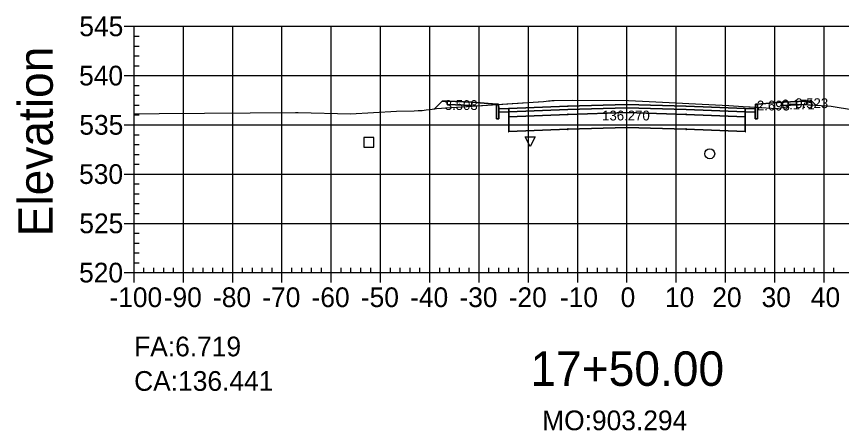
# Model space of a CAD drawing. Extents: x 704834 to 709892, y 372981 to 377533.
# Drawn here: x 704913 to 705080.4, y 374150.8 to 374234.8 of the extents above; entities that cross this region are included whole.
import ezdxf

# ---------------------------------------------------------------- set-up
doc = ezdxf.new("R2010")
doc.units = 0
for name, color, linetype in [('1', 7, 'Continuous'), ('10', 7, 'Continuous'), ('13', 7, 'Continuous'), ('14', 7, 'Continuous'), ('57', 7, 'Continuous'), ('59', 7, 'Continuous'), ('60', 7, 'Continuous'), ('Default_Xsect', 7, 'Continuous'), ('Existing', 7, 'Continuous')]:
    doc.layers.add(name, color=color, linetype=linetype)

msp = doc.modelspace()

# ---------------------------------------------------------------- linework, layer by layer
for points in [[(704999.37, 374217.61), (704997.84, 374216.07)], [(705000.37, 374217.65), (704999.37, 374217.61)], [(705010.37, 374217.05), (705005.37, 374217.45)], [(705063.37, 374217.05), (705068.37, 374217.45)], [(705073.37, 374217.65), (705074.37, 374217.61)], [(705074.37, 374217.61), (705075.16, 374216.82)]]:
    msp.add_lwpolyline(points)
for points in [[(705005.37, 374217.45), (705000.37, 374217.65), (705000.37, 374216.98), (705005.37, 374216.78)], [(705068.37, 374216.78), (705073.37, 374216.98), (705073.37, 374217.65), (705068.37, 374217.45)], [(705010.87, 374216.05), (705010.79, 374217.05), (705010.37, 374217.05), (705010.37, 374214.05), (705010.87, 374214.05)], [(705012.87, 374216.13), (705010.87, 374216.05), (705010.87, 374215.38), (705012.87, 374215.46)], [(705036.87, 374216.3), (705048.87, 374215.94), (705060.87, 374215.46), (705060.87, 374216.13), (705048.87, 374216.61), (705036.87, 374216.97), (705024.87, 374216.61), (705012.87, 374216.13), (705012.87, 374215.46), (705024.87, 374215.94)], [(705036.87, 374215.3), (705048.87, 374214.94), (705060.87, 374214.46), (705060.87, 374215.46), (705048.87, 374215.94), (705036.87, 374216.3), (705024.87, 374215.94), (705012.87, 374215.46), (705012.87, 374214.46), (705024.87, 374214.94)], [(705036.82, 374216.25), (705036.92, 374216.25), (705036.92, 374216.35), (705036.82, 374216.35)], [(705060.87, 374215.46), (705062.87, 374215.38), (705062.87, 374216.05), (705060.87, 374216.13)], [(705062.87, 374214.05), (705063.37, 374214.05), (705063.37, 374217.05), (705062.96, 374217.05), (705062.87, 374216.05)], [(705012.82, 374214.41), (705012.92, 374214.41), (705012.92, 374214.51), (705012.82, 374214.51)], [(705036.87, 374212.3), (705048.87, 374211.94), (705060.87, 374211.46), (705060.87, 374214.46), (705048.87, 374214.94), (705036.87, 374215.3), (705024.87, 374214.94), (705012.87, 374214.46), (705012.87, 374211.46), (705024.87, 374211.94)], [(705024.82, 374214.89), (705024.92, 374214.89), (705024.92, 374214.99), (705024.82, 374214.99)], [(705036.82, 374215.25), (705036.92, 374215.25), (705036.92, 374215.35), (705036.82, 374215.35)], [(705048.82, 374214.89), (705048.92, 374214.89), (705048.92, 374214.99), (705048.82, 374214.99)], [(705060.82, 374214.41), (705060.92, 374214.41), (705060.92, 374214.51), (705060.82, 374214.51)], [(705012.82, 374211.41), (705012.92, 374211.41), (705012.92, 374211.51), (705012.82, 374211.51)], [(705024.82, 374211.89), (705024.92, 374211.89), (705024.92, 374211.99), (705024.82, 374211.99)], [(705036.82, 374212.25), (705036.92, 374212.25), (705036.92, 374212.35), (705036.82, 374212.35)], [(705048.82, 374211.89), (705048.92, 374211.89), (705048.92, 374211.99), (705048.82, 374211.99)], [(705060.82, 374211.41), (705060.92, 374211.41), (705060.92, 374211.51), (705060.82, 374211.51)]]:
    msp.add_lwpolyline(points, close=True)
at = {"layer": '1'}
for points in [[(704997.84, 374216.07), (704998.21, 374216.12), (705010.37, 374216.94), (705010.37, 374217.05), (705005.37, 374217.45), (705005.37, 374216.78), (705000.37, 374216.98), (705000.37, 374217.65), (704999.37, 374217.61)], [(705010.37, 374216.94), (705019.91, 374217.59), (705020.46, 374217.64), (705020.92, 374217.68), (705021.31, 374217.72), (705021.62, 374217.74), (705021.87, 374217.76), (705022.1, 374217.79), (705025.85, 374217.85), (705037.2, 374217.76), (705040.04, 374217.62), (705057.55, 374216.75), (705060.46, 374216.56), (705063.37, 374216.38), (705063.37, 374214.05), (705062.87, 374214.05), (705062.87, 374215.38), (705060.87, 374215.46), (705060.87, 374214.46), (705060.87, 374211.46), (705048.87, 374211.94), (705036.87, 374212.3), (705024.87, 374211.94), (705012.87, 374211.46), (705012.87, 374214.46), (705012.87, 374215.46), (705010.87, 374215.38), (705010.87, 374214.05), (705010.37, 374214.05)], [(705063.37, 374216.38), (705065.09, 374216.27), (705067.21, 374216.13), (705069.25, 374216.5), (705069.69, 374216.83), (705068.37, 374216.78), (705068.37, 374217.45), (705063.37, 374217.05)], [(705072.77, 374216.96), (705075.16, 374216.82), (705074.37, 374217.61), (705073.37, 374217.65), (705073.37, 374216.98)], [(705069.69, 374216.83), (705070, 374217.06), (705072.36, 374216.98), (705072.77, 374216.96)], [(705017.22, 374208.41), (705016.22, 374210.41), (705018.22, 374210.41)]]:
    msp.add_lwpolyline(points, close=True, dxfattribs=at)
at = {"layer": '10'}
msp.add_lwpolyline([(704983.5, 374208.27), (704985.5, 374208.27), (704985.5, 374210.27), (704983.5, 374210.27)], close=True, dxfattribs=at)
at = {"layer": '13'}
msp.add_circle((705053.67, 374206.94), 1, dxfattribs=at)
at = {"layer": '14'}
for points in [[(704997.84, 374216.07), (704997.84, 374216.12), (704997.84, 374216.07), (704997.79, 374216.07), (704997.84, 374216.07), (704997.84, 374216.02), (704997.84, 374216.07), (704997.89, 374216.07)], [(705012.87, 374216.13), (705012.87, 374216.18), (705012.87, 374216.13), (705012.82, 374216.13), (705012.87, 374216.13), (705012.87, 374216.08), (705012.87, 374216.13), (705012.92, 374216.13)], [(705024.87, 374216.61), (705024.87, 374216.66), (705024.87, 374216.61), (705024.82, 374216.61), (705024.87, 374216.61), (705024.87, 374216.56), (705024.87, 374216.61), (705024.92, 374216.61)], [(705036.87, 374216.97), (705036.87, 374217.02), (705036.87, 374216.97), (705036.82, 374216.97), (705036.87, 374216.97), (705036.87, 374216.92), (705036.87, 374216.97), (705036.92, 374216.97)], [(705048.87, 374216.61), (705048.87, 374216.66), (705048.87, 374216.61), (705048.82, 374216.61), (705048.87, 374216.61), (705048.87, 374216.56), (705048.87, 374216.61), (705048.92, 374216.61)], [(705060.87, 374216.13), (705060.87, 374216.18), (705060.87, 374216.13), (705060.82, 374216.13), (705060.87, 374216.13), (705060.87, 374216.08), (705060.87, 374216.13), (705060.92, 374216.13)], [(705075.16, 374216.82), (705075.16, 374216.87), (705075.16, 374216.82), (705075.11, 374216.82), (705075.16, 374216.82), (705075.16, 374216.77), (705075.16, 374216.82), (705075.21, 374216.82)]]:
    msp.add_lwpolyline(points, dxfattribs=at)
at = {"layer": '57'}
for p, q in [((704934.87, 374232.82), (704936.87, 374232.82)), ((704936.87, 374232.82), (705136.87, 374232.82)), ((704936.87, 374182.82), (704936.87, 374232.82)), ((704936.87, 374182.82), (704936.87, 374232.82)), ((704946.87, 374182.82), (704946.87, 374232.82)), ((704956.87, 374182.82), (704956.87, 374232.82)), ((704966.87, 374182.82), (704966.87, 374232.82)), ((704976.87, 374182.82), (704976.87, 374232.82)), ((704986.87, 374182.82), (704986.87, 374232.82)), ((704996.87, 374182.82), (704996.87, 374232.82)), ((705006.87, 374182.82), (705006.87, 374232.82)), ((705016.87, 374182.82), (705016.87, 374232.82)), ((705026.87, 374182.82), (705026.87, 374232.82)), ((705036.87, 374182.82), (705036.87, 374232.82)), ((705046.87, 374182.82), (705046.87, 374232.82)), ((705056.87, 374182.82), (705056.87, 374232.82)), ((705066.87, 374182.82), (705066.87, 374232.82)), ((705076.87, 374182.82), (705076.87, 374232.82)), ((704936.87, 374230.82), (704937.87, 374230.82)), ((704936.87, 374228.82), (704937.87, 374228.82)), ((704936.87, 374226.82), (704937.87, 374226.82)), ((704936.87, 374224.82), (704937.87, 374224.82)), ((704934.87, 374222.82), (704936.87, 374222.82)), ((704936.87, 374222.82), (705136.87, 374222.82)), ((704936.87, 374220.82), (704937.87, 374220.82)), ((704936.87, 374218.82), (704937.87, 374218.82)), ((704936.87, 374216.82), (704937.87, 374216.82)), ((704936.87, 374214.82), (704937.87, 374214.82)), ((704934.87, 374212.82), (704936.87, 374212.82)), ((704936.87, 374212.82), (705136.87, 374212.82)), ((704936.87, 374210.82), (704937.87, 374210.82)), ((704936.87, 374208.82), (704937.87, 374208.82)), ((704936.87, 374206.82), (704937.87, 374206.82)), ((704936.87, 374204.82), (704937.87, 374204.82)), ((704934.87, 374202.82), (704936.87, 374202.82)), ((704936.87, 374202.82), (705136.87, 374202.82)), ((704936.87, 374200.82), (704937.87, 374200.82)), ((704936.87, 374198.82), (704937.87, 374198.82)), ((704936.87, 374196.82), (704937.87, 374196.82)), ((704936.87, 374194.82), (704937.87, 374194.82)), ((704934.87, 374192.82), (704936.87, 374192.82)), ((704936.87, 374192.82), (705136.87, 374192.82)), ((704936.87, 374190.82), (704937.87, 374190.82)), ((704936.87, 374188.82), (704937.87, 374188.82)), ((704936.87, 374186.82), (704937.87, 374186.82)), ((704936.87, 374184.82), (704937.87, 374184.82)), ((704934.87, 374182.82), (704936.87, 374182.82)), ((704936.87, 374182.82), (705136.87, 374182.82)), ((704936.87, 374182.82), (705136.87, 374182.82)), ((704936.87, 374180.82), (704936.87, 374182.82)), ((704938.87, 374182.82), (704938.87, 374183.82)), ((704940.87, 374182.82), (704940.87, 374183.82)), ((704942.87, 374182.82), (704942.87, 374183.82)), ((704944.87, 374182.82), (704944.87, 374183.82)), ((704946.87, 374180.82), (704946.87, 374182.82)), ((704948.87, 374182.82), (704948.87, 374183.82)), ((704950.87, 374182.82), (704950.87, 374183.82)), ((704952.87, 374182.82), (704952.87, 374183.82)), ((704954.87, 374182.82), (704954.87, 374183.82)), ((704956.87, 374180.82), (704956.87, 374182.82)), ((704958.87, 374182.82), (704958.87, 374183.82)), ((704960.87, 374182.82), (704960.87, 374183.82)), ((704962.87, 374182.82), (704962.87, 374183.82)), ((704964.87, 374182.82), (704964.87, 374183.82)), ((704966.87, 374180.82), (704966.87, 374182.82)), ((704968.87, 374182.82), (704968.87, 374183.82)), ((704970.87, 374182.82), (704970.87, 374183.82)), ((704972.87, 374182.82), (704972.87, 374183.82)), ((704974.87, 374182.82), (704974.87, 374183.82)), ((704976.87, 374180.82), (704976.87, 374182.82)), ((704978.87, 374182.82), (704978.87, 374183.82)), ((704980.87, 374182.82), (704980.87, 374183.82)), ((704982.87, 374182.82), (704982.87, 374183.82)), ((704984.87, 374182.82), (704984.87, 374183.82)), ((704986.87, 374180.82), (704986.87, 374182.82)), ((704988.87, 374182.82), (704988.87, 374183.82)), ((704990.87, 374182.82), (704990.87, 374183.82)), ((704992.87, 374182.82), (704992.87, 374183.82)), ((704994.87, 374182.82), (704994.87, 374183.82)), ((704996.87, 374180.82), (704996.87, 374182.82)), ((704998.87, 374182.82), (704998.87, 374183.82)), ((705000.87, 374182.82), (705000.87, 374183.82)), ((705002.87, 374182.82), (705002.87, 374183.82)), ((705004.87, 374182.82), (705004.87, 374183.82)), ((705006.87, 374180.82), (705006.87, 374182.82)), ((705008.87, 374182.82), (705008.87, 374183.82)), ((705010.87, 374182.82), (705010.87, 374183.82)), ((705012.87, 374182.82), (705012.87, 374183.82)), ((705014.87, 374182.82), (705014.87, 374183.82)), ((705016.87, 374180.82), (705016.87, 374182.82)), ((705018.87, 374182.82), (705018.87, 374183.82)), ((705020.87, 374182.82), (705020.87, 374183.82)), ((705022.87, 374182.82), (705022.87, 374183.82)), ((705024.87, 374182.82), (705024.87, 374183.82)), ((705026.87, 374180.82), (705026.87, 374182.82)), ((705028.87, 374182.82), (705028.87, 374183.82)), ((705030.87, 374182.82), (705030.87, 374183.82)), ((705032.87, 374182.82), (705032.87, 374183.82)), ((705034.87, 374182.82), (705034.87, 374183.82)), ((705036.87, 374180.82), (705036.87, 374182.82)), ((705038.87, 374182.82), (705038.87, 374183.82)), ((705040.87, 374182.82), (705040.87, 374183.82)), ((705042.87, 374182.82), (705042.87, 374183.82)), ((705044.87, 374182.82), (705044.87, 374183.82)), ((705046.87, 374180.82), (705046.87, 374182.82)), ((705048.87, 374182.82), (705048.87, 374183.82)), ((705050.87, 374182.82), (705050.87, 374183.82)), ((705052.87, 374182.82), (705052.87, 374183.82)), ((705054.87, 374182.82), (705054.87, 374183.82)), ((705056.87, 374180.82), (705056.87, 374182.82)), ((705058.87, 374182.82), (705058.87, 374183.82)), ((705060.87, 374182.82), (705060.87, 374183.82)), ((705062.87, 374182.82), (705062.87, 374183.82)), ((705064.87, 374182.82), (705064.87, 374183.82)), ((705066.87, 374180.82), (705066.87, 374182.82)), ((705068.87, 374182.82), (705068.87, 374183.82)), ((705070.87, 374182.82), (705070.87, 374183.82)), ((705072.87, 374182.82), (705072.87, 374183.82)), ((705074.87, 374182.82), (705074.87, 374183.82)), ((705076.87, 374180.82), (705076.87, 374182.82)), ((705078.87, 374182.82), (705078.87, 374183.82))]:
    msp.add_line(p, q, dxfattribs=at)
at = {"layer": 'Default_Xsect'}
msp.add_lwpolyline([(704997.84, 374216.07), (704999.37, 374217.61), (705000.37, 374217.65), (705005.37, 374217.45), (705010.37, 374217.05), (705010.79, 374217.05), (705010.87, 374216.05), (705012.87, 374216.13), (705024.87, 374216.61), (705036.87, 374216.97), (705048.87, 374216.61), (705060.87, 374216.13), (705062.87, 374216.05), (705062.96, 374217.05), (705063.37, 374217.05), (705068.37, 374217.45), (705073.37, 374217.65), (705074.37, 374217.61), (705075.16, 374216.82)], dxfattribs=at)
at = {"layer": 'Existing'}
msp.add_lwpolyline([(704936.87, 374215.08), (704941.92, 374215.1), (704969.59, 374215.3), (704969.99, 374215.3), (704970.09, 374215.3), (704970.17, 374215.3), (704980.75, 374215.07), (704990.08, 374215.57), (704993.68, 374215.66), (704994.5, 374215.7), (704995.32, 374215.76), (704996.1, 374215.84), (704996.85, 374215.93), (704998.21, 374216.12), (705019.91, 374217.59), (705020.46, 374217.64), (705020.92, 374217.68), (705021.31, 374217.72), (705021.62, 374217.74), (705021.87, 374217.76), (705022.1, 374217.79), (705025.85, 374217.85), (705037.2, 374217.76), (705040.04, 374217.62), (705057.55, 374216.75), (705060.46, 374216.56), (705065.09, 374216.27), (705067.21, 374216.13), (705069.25, 374216.5), (705070, 374217.06), (705072.36, 374216.98), (705077.56, 374216.68), (705078.31, 374216.64), (705082.81, 374215.87)], dxfattribs=at)

# ---------------------------------------------------------------- texts
msp.add_text('CA:136.441', height=4).set_placement((704936.87, 374158.82))
at = {"layer": '1'}
msp.add_text('17+50.00', height=7, dxfattribs=at).set_placement((705017.28, 374159.82))
at = {"layer": '14'}
for p in [(705000.34, 374217.6), (705073.34, 374217.6), (705000.34, 374216.93), (705005.34, 374216.73), (705068.34, 374216.73), (705073.34, 374216.93)]:
    msp.add_text('+', height=0.1, dxfattribs=at).set_placement(p)
at = {"layer": '57'}
for s, p in [('545', (704925.75, 374230.82)), ('540', (704925.7, 374220.82)), ('535', (704925.75, 374210.82)), ('530', (704925.7, 374200.82)), ('525', (704925.75, 374190.82)), ('520', (704925.7, 374180.82)), ('-100', (704931.86, 374175.82)), ('-90', (704942.87, 374175.82)), ('-80', (704952.87, 374175.82)), ('-70', (704962.87, 374175.82)), ('-60', (704972.87, 374175.82)), ('-50', (704982.87, 374175.82)), ('-40', (704992.87, 374175.82)), ('-30', (705002.87, 374175.82)), ('-20', (705012.87, 374175.82)), ('-10', (705023.26, 374175.82)), ('0', (705035.58, 374175.82)), ('10', (705044.57, 374175.82)), ('20', (705054.18, 374175.82)), ('30', (705064.18, 374175.82)), ('40', (705074.18, 374175.82))]:
    msp.add_text(s, height=4, dxfattribs=at).set_placement(p)
at = {"layer": '59'}
for s, height, p in [('3.503', 2, (704999.89, 374215.83)), ('2.693', 2, (705063.23, 374215.74)), ('0.171', 2, (705068.27, 374215.95)), ('0.523', 2, (705071, 374216.21)), ('136.270', 2, (705031.83, 374213.71)), ('FA:6.719', 4, (704936.87, 374165.82)), ('MO:903.294', 4, (705019.66, 374150.82))]:
    msp.add_text(s, height=height, dxfattribs=at).set_placement(p)
at = {"layer": '60'}
msp.add_text('Elevation', height=7, rotation=90, dxfattribs=at).set_placement((704920.37, 374190.18))

doc.saveas('drawing.dxf')
